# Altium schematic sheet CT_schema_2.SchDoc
size 350 x 214 mm
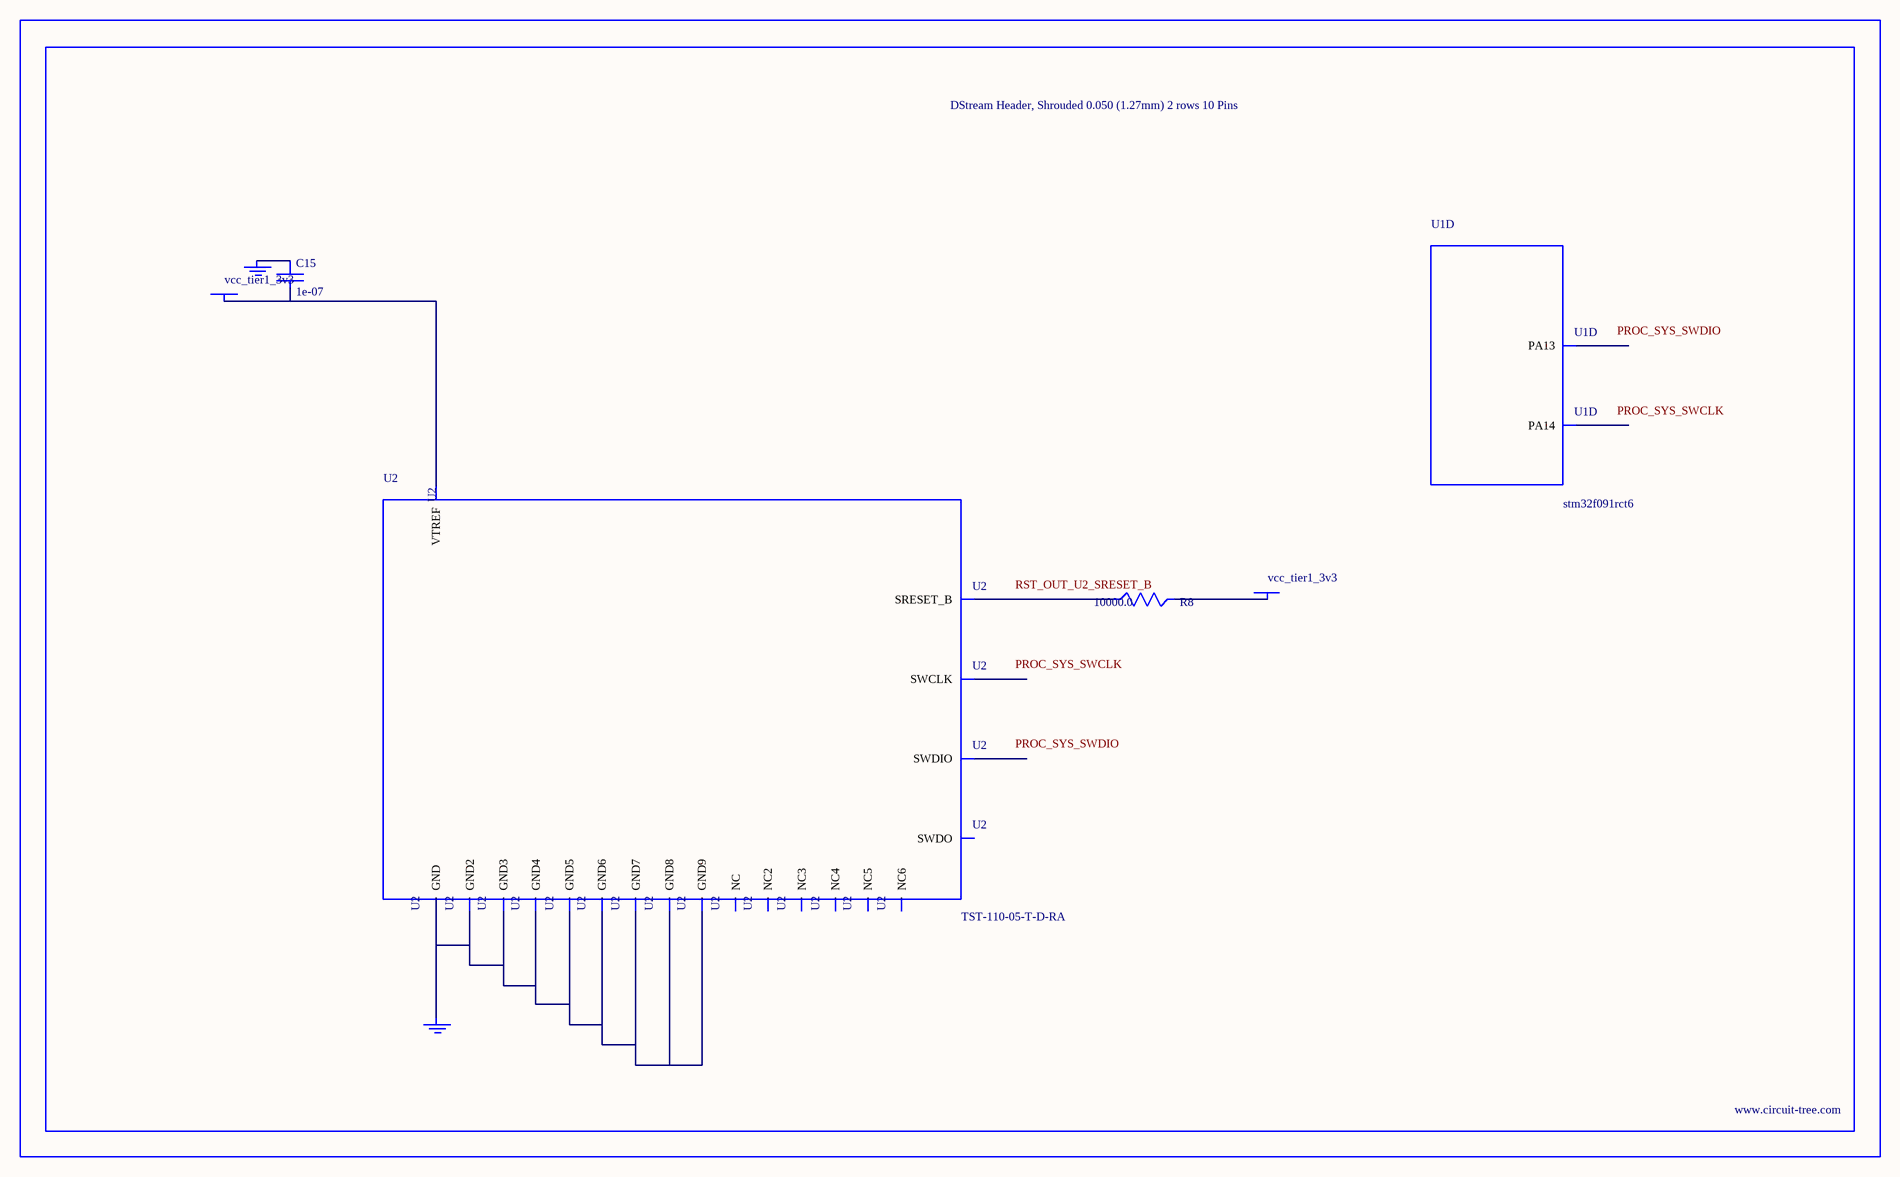
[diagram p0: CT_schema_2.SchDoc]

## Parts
BORDER1  (no value)
C15  1e-07  [C0402]
GND_INSTANCE_1_0  (no value)
GND_INSTANCE_1_1  (no value)
POWER_INSTANCE_1_0  vcc_tier1_3v3
POWER_INSTANCE_1_1  vcc_tier1_3v3
R8  10000.0  [R0603]
U1  stm32f091rct6  [LQFP64]  (part D of 7)
U2  TST-110-05-T-D-RA  [TST-110-05-T-D-RA]

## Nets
NetC15_1: C15.1 GND_INSTANCE_1_0.0(GND)
NetC15_2: C15.2 POWER_INSTANCE_1_0.0(PWR) U2.1(VTREF)
NetGND_INSTANCE_1_1_0: GND_INSTANCE_1_1.0(GND) U2.4(GND) U2.6(GND2) U2.8(GND3) U2.10(GND4) U2.12(GND5) U2.14(GND6) U2.16(GND7) U2.18(GND8) U2.20(GND9)
NetPOWER_INSTANCE_1_1_0: POWER_INSTANCE_1_1.0(PWR) R8.2
NetR8_1: R8.1 U2.15(SRESET_B)

Not connected (* = marked no-connect by the designer): U1 46(PA13) 49(PA14); U2 2(NC) 3(NC2) 5(NC3) 7(SWDIO) 9(SWCLK) 11(NC4) 13(SWDO) 17(NC5) 19(NC6)

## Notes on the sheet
- Labels drawn without touching a wire or pin: PROC_SYS_SWCLK, PROC_SYS_SWDIO, RST_OUT_U2_SRESET_B

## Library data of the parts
BORDER1 = BORDER_PAGE1
C15 = C0402C104K3RACTU
GND_INSTANCE_1_0 GND_INSTANCE_1_1 = GND
POWER_INSTANCE_1_0 POWER_INSTANCE_1_1 = PWR
R8 = RC0603JR-0710KL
